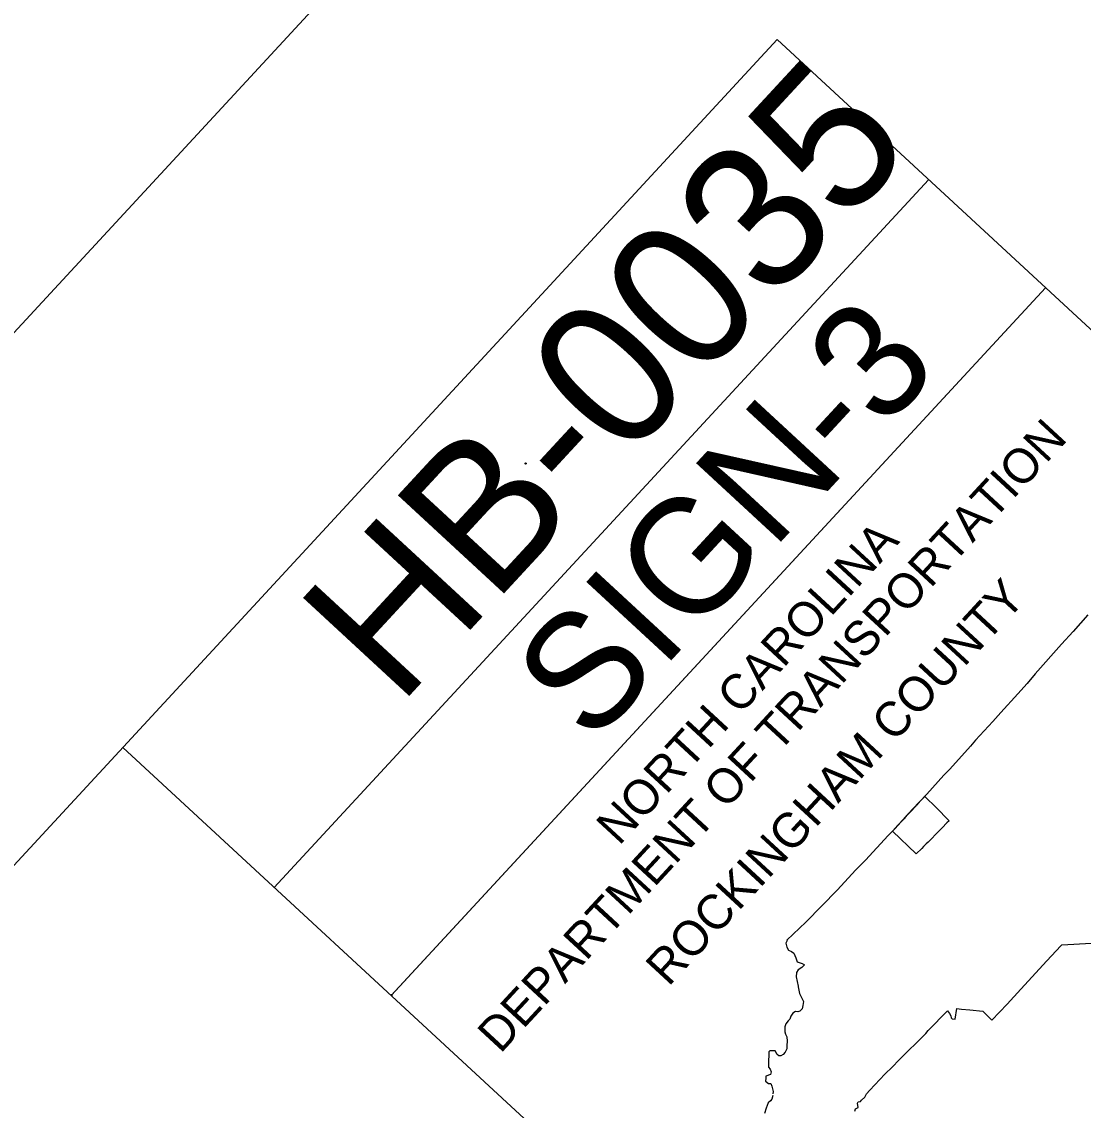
# Model space of a CAD drawing. Extents: x 1768064 to 1770025, y 999327 to 1001342.
# Drawn here: x 1769141.4 to 1769251.5, y 1001157.8 to 1001270.8 of the extents above; entities that cross this region are included whole.
import ezdxf

# ---------------------------------------------------------------- set-up
doc = ezdxf.new("R2010")
doc.units = 0
for name, color, linetype in [('_CIVIL_CONSTRUCTION', 7, 'Continuous'), ('E_NCDOT_Horizontal_Alignment_Curve', 7, 'Continuous'), ('E_NCDOT_Terrain_Model_Contour_Imported', 7, 'Continuous'), ('E_NCDOT_Terrain_Model_Flow_Arrows', 7, 'Continuous'), ('E_NCDOT_Terrain_Model_Points_High', 7, 'Continuous'), ('E_NCDOT_Terrain_Model_Spot_Elevation', 7, 'Continuous'), ('E_NCDOT_Terrain_Model_Void', 7, 'Continuous')]:
    doc.layers.add(name, color=color, linetype=linetype)

msp = doc.modelspace()

# ---------------------------------------------------------------- linework, layer by layer
at = {"layer": '_CIVIL_CONSTRUCTION'}
msp.add_lwpolyline([(1768063.72, 1000073.53), (1769217.66, 1001321.9), (1770025.42, 1000575.24), (1768871.49, 999326.87)], close=True, dxfattribs=at)
at = {"layer": 'E_NCDOT_Horizontal_Alignment_Curve'}
msp.add_lwpolyline([(1769237.52, 1001187.94), (1769237.59, 1001187.87), (1769237.37, 1001187.64), (1769236.87, 1001187.13), (1769236.69, 1001186.94), (1769236.44, 1001186.68), (1769236.39, 1001186.63), (1769235.58, 1001185.81), (1769235.55, 1001185.79), (1769235.52, 1001185.76), (1769235.41, 1001185.65), (1769235.23, 1001185.47), (1769234.95, 1001185.19), (1769234.75, 1001184.99), (1769234.18, 1001184.42), (1769231.73, 1001186.77), (1769231.91, 1001186.96), (1769232.07, 1001187.14), (1769232.24, 1001187.32), (1769232.32, 1001187.41), (1769232.45, 1001187.55), (1769232.49, 1001187.6), (1769232.56, 1001187.68), (1769232.72, 1001187.85), (1769232.77, 1001187.9), (1769232.85, 1001187.99), (1769232.91, 1001188.06), (1769232.99, 1001188.14), (1769233.11, 1001188.26), (1769233.26, 1001188.43), (1769233.36, 1001188.54), (1769233.45, 1001188.64), (1769233.51, 1001188.71), (1769233.53, 1001188.73), (1769233.56, 1001188.76), (1769233.58, 1001188.78), (1769233.6, 1001188.8), (1769233.63, 1001188.83), (1769233.65, 1001188.85), (1769233.67, 1001188.87), (1769233.68, 1001188.89), (1769233.7, 1001188.91), (1769233.7, 1001188.91), (1769233.73, 1001188.94), (1769233.75, 1001188.96), (1769233.76, 1001188.98), (1769233.78, 1001189), (1769233.8, 1001189.02), (1769233.82, 1001189.04), (1769233.84, 1001189.06), (1769233.86, 1001189.08), (1769233.88, 1001189.11), (1769233.9, 1001189.13), (1769233.92, 1001189.14), (1769233.93, 1001189.16), (1769233.94, 1001189.17), (1769233.96, 1001189.19), (1769233.98, 1001189.22), (1769234, 1001189.23), (1769234.01, 1001189.25), (1769234.02, 1001189.26), (1769234.03, 1001189.27), (1769234.05, 1001189.29), (1769234.07, 1001189.31), (1769234.1, 1001189.34), (1769234.11, 1001189.35), (1769234.13, 1001189.37), (1769234.14, 1001189.38), (1769234.15, 1001189.4), (1769234.17, 1001189.42), (1769234.18, 1001189.43), (1769234.2, 1001189.45), (1769234.22, 1001189.47), (1769234.24, 1001189.5), (1769234.27, 1001189.53), (1769234.3, 1001189.56), (1769234.35, 1001189.61), (1769234.35, 1001189.62), (1769234.37, 1001189.63), (1769234.38, 1001189.65), (1769234.41, 1001189.68), (1769234.43, 1001189.7), (1769234.48, 1001189.76), (1769234.51, 1001189.78), (1769234.51, 1001189.79), (1769234.54, 1001189.82), (1769234.57, 1001189.86), (1769235.08, 1001190.39), (1769236.27, 1001189.2), (1769237.52, 1001187.94)], close=True, dxfattribs=at)
at = {"layer": 'E_NCDOT_Terrain_Model_Contour_Imported'}
msp.add_line((1769247.58, 1001243.17), (1769179.75, 1001169.78), dxfattribs=at)
msp.add_circle((1769179.75, 1001169.78), 0.06, dxfattribs=at)
msp.add_circle((1769179.75, 1001169.78), 0.06, dxfattribs=at)
msp.add_circle((1769179.75, 1001169.78), 0.06, dxfattribs=at)
at = {"layer": 'E_NCDOT_Terrain_Model_Flow_Arrows'}
msp.add_line((1768063.72, 1000073.53), (1769217.66, 1001321.9), dxfattribs=at)
msp.add_circle((1769193.66, 1001224.92), 0.06, dxfattribs=at)
at = {"layer": 'E_NCDOT_Terrain_Model_Spot_Elevation'}
for p, q in [((1769219.74, 1001268.91), (1768116.72, 1000075.62)), ((1769972.42, 1000573.14), (1769219.74, 1001268.91)), ((1769235.47, 1001254.37), (1769167.59, 1001180.94)), ((1769247.58, 1001243.17), (1769179.71, 1001169.74)), ((1769247.58, 1001243.17), (1769179.71, 1001169.74)), ((1769904.54, 1000499.71), (1769151.86, 1001195.48))]:
    msp.add_line(p, q, dxfattribs=at)
at = {"layer": 'E_NCDOT_Terrain_Model_Void'}
for points in [[(1769251.97, 1001209.23), (1769250.46, 1001207.5), (1769249.27, 1001206.2), (1769246.52, 1001203.09), (1769245.68, 1001202.12), (1769244.73, 1001201.04), (1769242.96, 1001199.09), (1769242.13, 1001198.17), (1769240.33, 1001196.21), (1769239.83, 1001195.59), (1769237.67, 1001193.23), (1769237.05, 1001192.61), (1769235.3, 1001190.63), (1769233.79, 1001189.05), (1769231.73, 1001186.77), (1769231.28, 1001186.33), (1769228.92, 1001183.79), (1769227.93, 1001182.76), (1769226.35, 1001181.08), (1769226.01, 1001180.7), (1769222.74, 1001177.35), (1769220.77, 1001175.49), (1769220.78, 1001175.44), (1769220.66, 1001175.15), (1769220.75, 1001174.74), (1769220.93, 1001174.45), (1769221.23, 1001174.29), (1769221.5, 1001174.11), (1769221.69, 1001173.63), (1769221.82, 1001173.24), (1769222.14, 1001173.14), (1769222.36, 1001173.05), (1769222.6, 1001172.92), (1769222.3, 1001172.63), (1769221.93, 1001172.4), (1769221.76, 1001172.11), (1769221.73, 1001171.67), (1769221.94, 1001170.7), (1769221.94, 1001170.63), (1769222.09, 1001169.94), (1769222.5, 1001169.12), (1769222.41, 1001168.69), (1769222.35, 1001168.34), (1769222.1, 1001168.12), (1769221.9, 1001168.03), (1769221.66, 1001168.06), (1769221.38, 1001167.91), (1769221.16, 1001167.59), (1769221.06, 1001167.29), (1769220.9, 1001167.09), (1769220.65, 1001166.8), (1769220.56, 1001166.47), (1769220.56, 1001165.98), (1769220.61, 1001165.72), (1769220.75, 1001165.45), (1769220.79, 1001164.99), (1769220.76, 1001164.56), (1769220.75, 1001164.21), (1769220.57, 1001163.86), (1769220.38, 1001163.61), (1769220.13, 1001163.47), (1769219.93, 1001163.48), (1769219.76, 1001163.63), (1769219.55, 1001163.99), (1769219, 1001163.98), (1769218.9, 1001163.89), (1769218.85, 1001162.61), (1769218.87, 1001162.29), (1769219.04, 1001162.08), (1769219.12, 1001161.82), (1769219.07, 1001161.54), (1769218.59, 1001161.36), (1769218.57, 1001161.15), (1769218.54, 1001160.85), (1769218.87, 1001160.62), (1769219.11, 1001160.61), (1769219.2, 1001160.33), (1769219.35, 1001159.77), (1769219.32, 1001159.53)], [(1769227.82, 1001157.72), (1769227.88, 1001157.97), (1769228.16, 1001158.11), (1769228.09, 1001158.57), (1769228.15, 1001158.69), (1769228.39, 1001158.75), (1769228.52, 1001158.86), (1769228.86, 1001159.18), (1769229.02, 1001159.54), (1769229.37, 1001159.91), (1769230.92, 1001161.56), (1769231.72, 1001162.35), (1769232.37, 1001163.02), (1769235.17, 1001165.8), (1769235.42, 1001166.11), (1769237.42, 1001168.15), (1769237.63, 1001167.87), (1769237.77, 1001167.63), (1769237.8, 1001167.42), (1769237.92, 1001167.33), (1769238.22, 1001167.27), (1769238.41, 1001168.38), (1769238.88, 1001168.32), (1769239.74, 1001168.24), (1769241.08, 1001168.1), (1769242.02, 1001167.17), (1769243.63, 1001168.85), (1769245.02, 1001170.4), (1769247.73, 1001173.32), (1769249.17, 1001174.89), (1769249.29, 1001175), (1769252.38, 1001175.18)], [(1769219.3, 1001159.36), (1769219.22, 1001158.98), (1769219.06, 1001158.81), (1769218.81, 1001158.59), (1769218.62, 1001158.06), (1769218.45, 1001157.49)]]:
    msp.add_lwpolyline(points, dxfattribs=at)

# ---------------------------------------------------------------- texts
at = {"layer": 'E_NCDOT_Terrain_Model_Contour_Imported'}
for s, height, p in [('DEPARTMENT OF TRANSPORTATION', 3.5979, (1769191.03, 1001163.62)), ('NORTH CAROLINA', 3.5979, (1769203.35, 1001185.2)), ('ROCKINGHAM COUNTY', 3.5978, (1769208.48, 1001170.57)), ('TRAFFIC CONTROL ENGINEER', 4.5573, (1769242.29, 1001115.13))]:
    msp.add_text(s, height=height, rotation=47.2512, dxfattribs=at).set_placement(p)
at = {"layer": 'E_NCDOT_Terrain_Model_Points_High'}
for s, height, p in [('HB-0035', 15, (1769180.47, 1001199.6)), ('SIGN-3', 12, (1769200.5, 1001195.55))]:
    msp.add_text(s, height=height, rotation=47.2512, dxfattribs=at).set_placement(p)

doc.saveas('drawing.dxf')
